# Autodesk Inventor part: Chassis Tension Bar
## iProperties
Shininess: 70.0
Angle Display Precision: 2
Document Length Units: 11269
Document Angle Units: 11279
Document Time Units: 11290
Document Mass Units: 11283
Document Length Units Precision: 3
Document Angle Units Precision: 2
Compacted: True
Created: 2001-08
Part Number: Chassis Tension Bar
Document SubType Name: Modeling
Designer: Martin Budgell
Density: 0.0
Volumn: 0.0
Area: 0.0
PropertySet Name: Model Information
Control State: 0
Master: False
Checked Out: False
Author: Martin Budgell
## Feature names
1. Extrusion1
2. Extrusion2
3. Loft1
4. Loft2
5. Mirror1
6. Extrusion3
